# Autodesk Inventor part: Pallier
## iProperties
Created: 2011-07
Part Number: Pallier
Document SubType Name: Modeling
Designer: domi
Density: 1 g/cm^3
Author: domi
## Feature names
1. Pallier [Extrusion]
